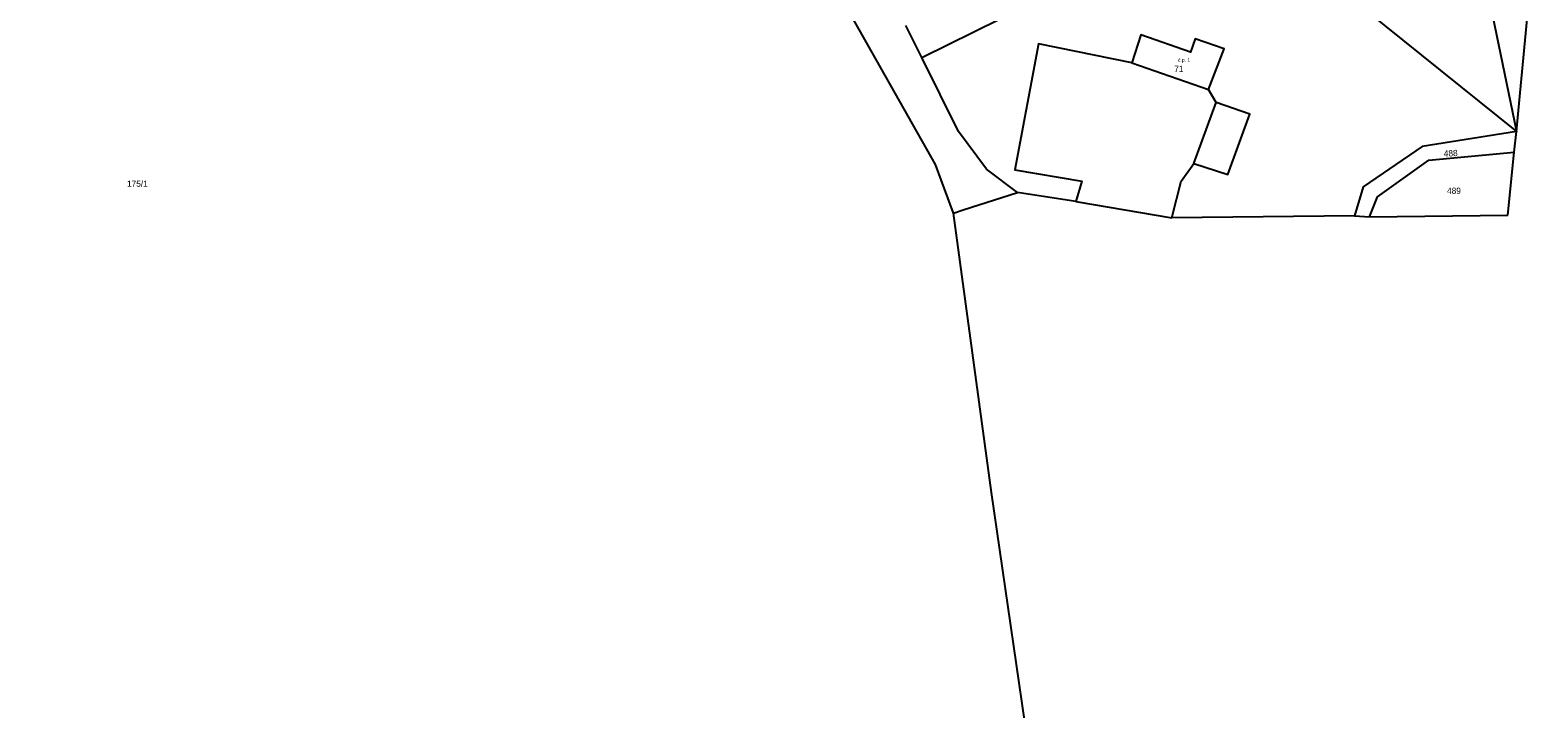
# Model space of a CAD drawing. Extents: x -880531 to -877616, y -1023932 to -1021350.
# Drawn here: x -878033.6 to -877620.6, y -1023450.8 to -1023264.8 of the extents above; entities that cross this region are included whole.
import ezdxf

# ---------------------------------------------------------------- set-up
doc = ezdxf.new("R2010")
doc.units = 0
for name, color, linetype in [('Definiční body', 7, 'Continuous'), ('Hranice parcel', 7, 'Continuous'), ('Parcelní čísla', 7, 'Continuous'), ('Polygon budovy', 7, 'Continuous'), ('Vnitřní kresba', 7, 'Continuous')]:
    doc.layers.add(name, color=color, linetype=linetype)

msp = doc.modelspace()

# ---------------------------------------------------------------- linework, layer by layer
at = {"layer": 'Hranice parcel'}
for p, q in [((-877637.98, -1023236.8), (-877626.37, -1023292.54)), ((-877789.32, -1023272.27), (-877793.71, -1023263.48)), ((-877627.03, -1023298.22), (-877626.37, -1023292.54)), ((-877628.79, -1023315.46), (-877627.03, -1023298.22)), ((-877778.02, -1023314.02), (-877763.08, -1023309.24)), ((-877747.08, -1023311.69), (-877763.08, -1023309.24)), ((-877780.67, -1023314.89), (-877778.02, -1023314.02)), ((-877747.08, -1023311.69), (-877720.84, -1023316.15)), ((-877670.8, -1023315.67), (-877720.84, -1023316.15)), ((-877670.8, -1023315.67), (-877666.71, -1023315.87)), ((-877666.71, -1023315.87), (-877628.79, -1023315.46))]:
    msp.add_line(p, q, dxfattribs=at)
for points in [[(-877780.67, -1023314.89), (-877785.52, -1023301.59), (-877820.27, -1023240.12), (-877836.64, -1023216.31), (-877856.74, -1023193.96), (-877904.17, -1023147.51), (-877968.01, -1023086.79), (-878004.38, -1023051.82), (-878026.11, -1023034.14), (-878098.6, -1022986.3), (-878150.98, -1022948.79), (-878185.16, -1022918.23), (-878216.86, -1022884.4), (-878262.44, -1022844.37)], [(-877626.37, -1023292.54), (-877620.56, -1023230.87), (-877620.8, -1023216.59)], [(-877789.32, -1023272.27), (-877704.02, -1023230.02), (-877626.37, -1023292.54)], [(-877720.84, -1023316.15), (-877718.23, -1023306.12), (-877714.77, -1023301.3), (-877705.52, -1023304.34), (-877699.44, -1023287.8), (-877708.7, -1023284.6), (-877710.8, -1023281.05), (-877706.52, -1023269.83), (-877714.4, -1023267.13), (-877715.68, -1023270.83), (-877729.3, -1023266.02), (-877731.79, -1023273.7)], [(-877731.79, -1023273.7), (-877757.31, -1023268.52), (-877763.86, -1023303.03), (-877745.5, -1023306.15), (-877747.08, -1023311.69)], [(-877763.08, -1023309.24), (-877771.58, -1023302.84), (-877779.23, -1023292.5), (-877789.32, -1023272.27)], [(-877626.37, -1023292.54), (-877652.24, -1023296.6), (-877668.39, -1023307.68), (-877670.8, -1023315.67)], [(-877666.71, -1023315.87), (-877664.48, -1023310.41), (-877650.45, -1023300.38), (-877627.03, -1023298.22)], [(-877705.27, -1023923.25), (-877699.07, -1023878.18), (-877700.35, -1023852.97), (-877733.94, -1023631.1), (-877746.99, -1023546.95), (-877758.83, -1023470.07), (-877770.2, -1023391.42), (-877780.67, -1023314.89)]]:
    msp.add_lwpolyline(points, dxfattribs=at)
at = {"layer": 'Polygon budovy'}
msp.add_lwpolyline([(-877714.4, -1023267.13), (-877715.68, -1023270.83), (-877729.3, -1023266.02), (-877731.79, -1023273.7), (-877710.8, -1023281.05), (-877706.52, -1023269.83)], close=True, dxfattribs=at)
at = {"layer": 'Vnitřní kresba'}
for p, q in [((-877731.79, -1023273.7), (-877710.8, -1023281.05)), ((-877714.77, -1023301.3), (-877708.7, -1023284.6))]:
    msp.add_line(p, q, dxfattribs=at)

# ---------------------------------------------------------------- texts
at = {"layer": 'Definiční body'}
msp.add_text('č.p. 1', height=1, dxfattribs=at).set_placement((-877719.16, -1023273.42))
at = {"layer": 'Parcelní čísla'}
for s, p in [('71', (-877720.16, -1023276.22)), ('175/1', (-878007.02, -1023307.69)), ('489', (-877645.43, -1023309.62))]:
    msp.add_text(s, height=1.7, dxfattribs=at).set_placement(p)
msp.add_text('488', height=1.7, rotation=3, dxfattribs=at).set_placement((-877646.285, -1023299.438))

doc.saveas('drawing.dxf')
